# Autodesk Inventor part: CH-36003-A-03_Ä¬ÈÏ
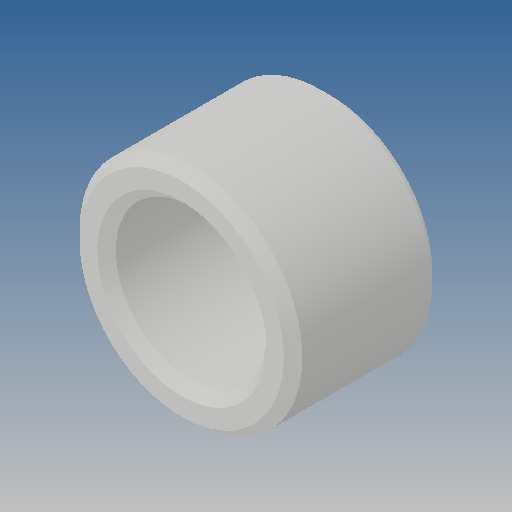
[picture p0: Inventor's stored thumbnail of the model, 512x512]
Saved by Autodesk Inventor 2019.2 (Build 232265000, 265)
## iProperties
Created: 2010-06
Part Number: CH-36003-A-03_Ä¬ÈÏ
Material: Ogólny
Document SubType Name: Modeling
Designer: CADENGINEERING4
Density: 1 g/cm^3
Appearance: Domyślna
Author: CADENGINEERING4
Revision Number: ÈÎºÎ
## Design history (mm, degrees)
feature "NONE"
node "Bryła1"
